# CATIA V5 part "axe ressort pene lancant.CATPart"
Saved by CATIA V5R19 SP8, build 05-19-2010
Part number: axe ressort pene lancant
Revision: ANY
Definition: UNKNOWN
Nomenclature: axe ressort pene lancant
Source: Unknown
Bounding box of the stored display mesh (mm): x 0 to 9, y -3 to 3, z -3 to 3
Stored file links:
  D:\Documents\1_Travail\1 - ac-limoges.fr\ac-limoges.fr\Emmanuel Maynard - STI2D_Turgot\2 -2I2D\2_SEQUENCE_Serrure_Biométrique\5-Spé_ITEC\Serrure_Bio_Eleve\axe ressort pene lancant.CATPart
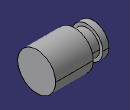
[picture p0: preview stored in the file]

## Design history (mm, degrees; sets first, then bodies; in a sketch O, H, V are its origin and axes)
Body1 "Révolution1" (main body)
  Solid1: solid without history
